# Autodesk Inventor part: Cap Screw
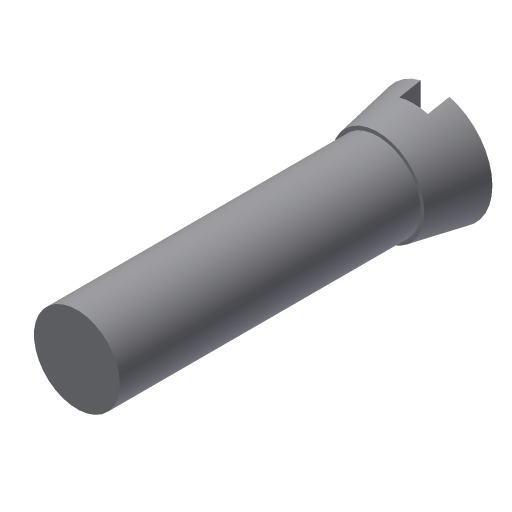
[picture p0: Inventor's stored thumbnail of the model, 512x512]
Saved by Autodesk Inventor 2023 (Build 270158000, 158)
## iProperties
Created: 2002-02
Part Number: Cap Screw
Document SubType Name: Modeling
Designer: ***
Density: 1 g/cm^3
Material: Generic
Appearance: Default
Control State: 0
Master: False
Checked Out: False
Shininess: 77.0
Length Units: 11269
Angle Units: 11279
Time Units: 11290
Mass Units: 11283
Length Display Precision: 3
Angle Display Precision: 2
Density: 0.0
Volumn: 0.0
Area: 0.0
PropertySet Name: Model Information
Author: ***
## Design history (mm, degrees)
sketch "Sketch1"
  geometry: L1 (0, 27.83)-(4, 27.83); L2 (4, 27.83)-(3.25, 23.83); L3 (3.25, 23.83)-(0, 23.83); L4 (0, 23.83)-(0, 27.83)
  constraints: 8 end point, 1 horizontal, 1 parallel, 1 perpendicular, 1 point on line
  dimensions: "d2" = 4 distance from line of L1 L2.end; "d5" = 8 diameter of L1.end L4; "d6" = 6.5 diameter of L3.start L4; "d14" = 4 distance of L3.end L1.start
revolve "Revolution1" sketch "Sketch1" stored, may be unused: angle "d7" = 90 deg
sketch "Sketch2"
  geometry: C1 r 3 at (0, 0)
  constraints: 1 centre point
  dimensions: "d8" = 6 diameter of C1
extrude "Extrusion1" join sketch "Sketch2" distance "d9" = 21; taper "d10" = 0 deg
sketch "Sketch3"
  geometry: L1 (-1, 28.967)-(1, 28.967); L2 (1, 28.967)-(1, 26.33); L3 (1, 26.33)-(-1, 26.33); L4 (-1, 26.33)-(-1, 28.967); L5 (-4, 27.83)-(4, 27.83) reference
  constraints: 8 end point, 2 parallel, 1 horizontal, 1 perpendicular
  dimensions: "d11" = 2 distance of L1.start L1.end; "d15" = 1.5 distance between parallel lines of L5 L3
extrude "Extrusion2" cut sketch "Sketch3" extent not by distance; stored distance "d12" = 24; taper "d13" = 0 deg
body "Solid1"
